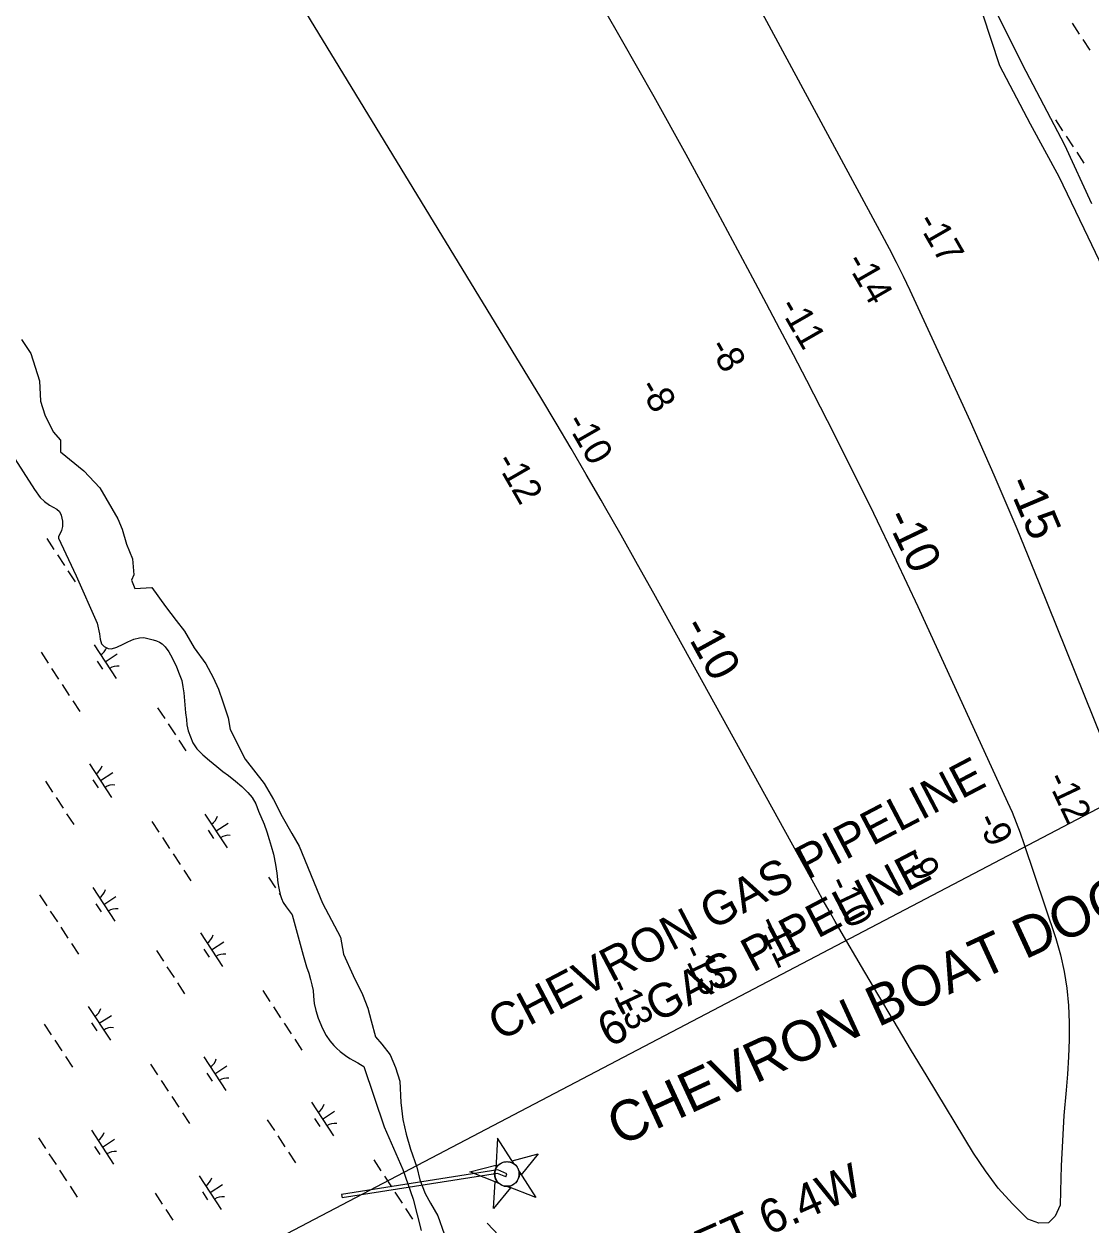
# Model space of a CAD drawing. Extents: x 3945642 to 3966284, y 206476 to 228921.
# Drawn here: x 3958060 to 3959382, y 212666 to 214156 of the extents above; entities that cross this region are included whole.
import ezdxf

# ---------------------------------------------------------------- set-up
doc = ezdxf.new("R2010")
doc.units = 0
for name, color, linetype in [('V-CHAN-DOCK', 7, 'Continuous'), ('V-CHAN-NAID', 7, 'Continuous'), ('V-RIVR-EDGE', 7, 'Continuous'), ('V-RIVR-RANG', 7, 'Continuous'), ('V-RRAP-DIKE', 7, 'Continuous'), ('V-RRAP-SILL-IDEN', 7, 'Continuous'), ('V-TOPO-DPTH', 7, 'Continuous'), ('V-TOPO-MINR', 7, 'Continuous'), ('V-TOPO-MINR-IDEN', 7, 'Continuous'), ('V-UTIL-IDEN', 7, 'Continuous'), ('V-UTIL-LINE', 7, 'Continuous'), ('V-WETL-SWMP', 7, 'Continuous')]:
    doc.layers.add(name, color=color, linetype=linetype)

msp = doc.modelspace()

# ---------------------------------------------------------------- linework, layer by layer
at = {"layer": 'V-CHAN-DOCK'}
for p, q in [((3958656.8, 212725.9), (3958658.4, 212729.6)), ((3958453.2, 212704.1), (3958453.9, 212700.2))]:
    msp.add_line(p, q, dxfattribs=at)
for points in [[(3958658.4, 212729.6), (3958647.1, 212734.6), (3958453.2, 212704.1)], [(3958656.8, 212725.9), (3958646.5, 212730.4), (3958453.9, 212700.2)]]:
    msp.add_lwpolyline(points, dxfattribs=at)
at = {"layer": 'V-CHAN-NAID'}
for points in [[(3958667.4, 212742), (3958646.7, 212774.1), (3958644.5, 212735.9), (3958645, 212736.9), (3958645.5, 212737.7), (3958646.1, 212738.6), (3958646.7, 212739.5), (3958647.2, 212740), (3958647.8, 212740.6), (3958648.3, 212741.1), (3958648.9, 212741.6), (3958649.6, 212742.1), (3958650.3, 212742.5), (3958651.2, 212743.1), (3958651.9, 212743.4), (3958652.9, 212743.9), (3958653.9, 212744.2), (3958654.8, 212744.5), (3958655.7, 212744.6), (3958656.6, 212744.8), (3958657.4, 212744.8), (3958658.5, 212744.9), (3958659.3, 212744.8), (3958660.2, 212744.8), (3958660.9, 212744.7), (3958661.8, 212744.5), (3958662.5, 212744.3), (3958663.6, 212744), (3958664.3, 212743.7), (3958665.2, 212743.3), (3958666, 212742.8), (3958666.7, 212742.4)], [(3958667.4, 212742), (3958664.8, 212746), (3958697.1, 212754.5), (3958676, 212728.6), (3958673.4, 212732.6), (3958673.2, 212733.5), (3958672.9, 212734.5), (3958672.5, 212735.5), (3958672.1, 212736.4), (3958671.8, 212736.9), (3958671.4, 212737.6), (3958670.9, 212738.3), (3958670.5, 212738.9), (3958669.9, 212739.6), (3958669.5, 212740.1), (3958668.8, 212740.8), (3958668.2, 212741.3), (3958667.8, 212741.6)], [(3958648.1, 212718.4), (3958612.4, 212732.2), (3958644.8, 212740.7), (3958644.5, 212735.9), (3958644.3, 212735.4), (3958643.9, 212734.3), (3958643.6, 212733.4), (3958643.4, 212732.4), (3958643.2, 212731.5), (3958643.2, 212730.6), (3958643.1, 212729.7), (3958643.2, 212728.7), (3958643.2, 212727.8), (3958643.4, 212726.8), (3958643.6, 212726), (3958643.8, 212725.2), (3958644.2, 212724.1), (3958644.5, 212723.4), (3958644.9, 212722.5), (3958645.3, 212721.8), (3958645.8, 212721), (3958646.3, 212720.3), (3958646.8, 212719.7), (3958647.5, 212719)], [(3958658.4, 212714.3), (3958662.9, 212712.6), (3958641.7, 212686.7), (3958643.6, 212720.1), (3958648.1, 212718.4), (3958648.7, 212717.8), (3958649.4, 212717.3), (3958650.4, 212716.6), (3958651.2, 212716.1), (3958652.2, 212715.7), (3958653.2, 212715.3), (3958654.1, 212714.9), (3958655, 212714.7), (3958655.9, 212714.5), (3958656.9, 212714.4), (3958657.8, 212714.4)], [(3958673.4, 212732.6), (3958694.1, 212700.5), (3958658.4, 212714.3), (3958659.3, 212714.4), (3958660.3, 212714.5), (3958661.2, 212714.6), (3958662.2, 212714.8), (3958663.1, 212715.1), (3958663.9, 212715.4), (3958664.8, 212715.8), (3958665.5, 212716.1), (3958666.5, 212716.7), (3958667.4, 212717.2), (3958668.2, 212717.9), (3958668.9, 212718.5), (3958669.7, 212719.3), (3958670.4, 212720.2), (3958671, 212721), (3958671.5, 212721.7), (3958672, 212722.7), (3958672.4, 212723.6), (3958672.8, 212724.5), (3958673.1, 212725.5), (3958673.3, 212726.4), (3958673.5, 212727.5), (3958673.6, 212728.6), (3958673.7, 212729.6), (3958673.6, 212730.7), (3958673.5, 212731.6)]]:
    msp.add_lwpolyline(points, close=True, dxfattribs=at)
msp.add_circle((3958658.4, 212729.6), 15.3, dxfattribs=at)
at = {"layer": 'V-RIVR-EDGE'}
for points in [[(3959247.9, 214168.6), (3959269.2, 214104.5), (3959307.2, 214032.1), (3959342.8, 213966.8), (3959378.5, 213892), (3959460.4, 213721), (3959496, 213645), (3959528, 213573.8), (3959594.5, 213443.2), (3959699, 213187.9), (3959765.5, 213045.5), (3959799.9, 212969.5), (3959840.3, 212872.1), (3959899.6, 212713.1), (3959916.3, 212675.1), (3959957.8, 212573)], [(3958056.4, 213764.5), (3958068.2, 213747.4), (3958078.7, 213713.3), (3958080, 213688.3), (3958085.3, 213671.2), (3958095.8, 213650.2), (3958105, 213639.7), (3958105, 213625.2), (3958133.9, 213601.6), (3958153.6, 213580.5), (3958176, 213542.4), (3958181.2, 213529.3), (3958186.5, 213510.9), (3958194.3, 213492.5), (3958195.7, 213472.8), (3958193, 213466.2), (3958197, 213455.7), (3958218, 213457), (3958235.1, 213433.3), (3958248.2, 213416.3), (3958258.7, 213403.1), (3958270.6, 213382.1), (3958285, 213362.4), (3958294.2, 213345.3), (3958300.8, 213330.8), (3958306.1, 213315.1), (3958312.6, 213295.4), (3958315.3, 213280.9), (3958333.7, 213244.1), (3958357.3, 213213.9), (3958369.1, 213194.2), (3958379.6, 213173.1), (3958391.5, 213152.1), (3958400.7, 213136.3), (3958429.6, 213065.4), (3958451.9, 213023.3), (3958455.9, 213002.3), (3958467.7, 212976), (3958479.5, 212952.4), (3958486.1, 212935.3), (3958490, 212919.5), (3958495.3, 212899.8), (3958503.2, 212890.6), (3958513.7, 212877.4), (3958520.3, 212861.7), (3958525.5, 212844.6), (3958526.8, 212818.3), (3958529.5, 212797.3), (3958533.4, 212778.9), (3958538.7, 212760.5), (3958546.5, 212738.1), (3958550.5, 212722.4), (3958557.1, 212705.3), (3958563.6, 212693.5), (3958572.8, 212677.7), (3958580.7, 212655.4)]]:
    msp.add_lwpolyline(points, dxfattribs=at)
at = {"layer": 'V-RRAP-DIKE'}
msp.add_lwpolyline([(3958633.8, 212668.5), (3958648.4, 212653.4)], dxfattribs=at)
at = {"layer": 'V-TOPO-DPTH'}
for points in [[(3959349.4, 212980.8), (3959352.6, 212959.9), (3959354.7, 212938.7), (3959355.5, 212917.4), (3959355.6, 212896.1), (3959354.8, 212874.8), (3959353.3, 212853.5), (3959351.5, 212833.5), (3959349, 212802.2), (3959347, 212770.9), (3959345.6, 212739.6), (3959344.7, 212708.2), (3959344.4, 212690.8), (3959338.2, 212677.4), (3959329.8, 212669.2), (3959318, 212668.8), (3959304.1, 212673.6), (3959285.2, 212692.4), (3959267.6, 212712.2), (3959251.7, 212733.5), (3959236.9, 212755.6), (3959179.4, 212850.4), (3959158.8, 212884.4), (3959138.4, 212918.6), (3959118.1, 212952.8), (3959097.9, 212987.1), (3959072.9, 213030), (3959065.4, 213042.9), (3959057.9, 213055.9), (3959050.6, 213069), (3959043.3, 213082), (3958860.3, 213413.6), (3958840.3, 213449.8), (3958820.2, 213485.8), (3958799.9, 213521.8), (3958779.5, 213557.8), (3958775.1, 213565.4), (3958756.7, 213597.4), (3958738.1, 213629.3), (3958719.3, 213661), (3958700.2, 213692.6), (3958323, 214311.9)], [(3958759.3, 214208.4), (3958800.1, 214137.4), (3958840.5, 214066.1), (3958880.1, 213994.4), (3958919.3, 213922.4), (3958962.9, 213841.1), (3958979.8, 213809.5), (3958996.5, 213777.9), (3959013.1, 213746.1), (3959029.6, 213714.3), (3959055.5, 213664), (3959084.5, 213606.7), (3959112.9, 213549.3), (3959140.6, 213491.4), (3959167.7, 213433.3), (3959279.1, 213190.9), (3959284.6, 213178.3), (3959289.9, 213165.5), (3959294.7, 213152.7), (3959299.3, 213139.7), (3959338.7, 213021.9), (3959344.6, 213001.5), (3959349.4, 212980.8)]]:
    msp.add_lwpolyline(points, dxfattribs=at)
at = {"layer": 'V-TOPO-MINR'}
for points in [[(3958708.5, 214663.2), (3959123.3, 213894.7), (3959132.3, 213877.7), (3959141.1, 213860.5), (3959149.6, 213843.2), (3959157.9, 213825.8), (3959202.7, 213729.3), (3959232.7, 213663.3), (3959262.1, 213597), (3959290.4, 213530.3), (3959318, 213463.2), (3959643.8, 212653.8)], [(3959349.4, 212980.8), (3959352.6, 212959.9), (3959354.7, 212938.7), (3959355.5, 212917.4), (3959355.6, 212896.1), (3959354.8, 212874.8), (3959353.3, 212853.5), (3959351.5, 212833.5), (3959349, 212802.2), (3959347, 212770.9), (3959345.6, 212739.6), (3959344.7, 212708.2), (3959344.4, 212690.8), (3959338.2, 212677.4), (3959329.8, 212669.2), (3959318, 212668.8), (3959304.1, 212673.6), (3959285.2, 212692.4), (3959267.6, 212712.2), (3959251.7, 212733.5), (3959236.9, 212755.6), (3959179.4, 212850.4), (3959158.8, 212884.4), (3959138.4, 212918.6), (3959118.1, 212952.8), (3959097.9, 212987.1), (3959072.9, 213030), (3959065.4, 213042.9), (3959057.9, 213055.9), (3959050.6, 213069), (3959043.3, 213082), (3958860.3, 213413.6), (3958840.3, 213449.8), (3958820.2, 213485.8), (3958799.9, 213521.8), (3958779.5, 213557.8), (3958775.1, 213565.4), (3958756.7, 213597.4), (3958738.1, 213629.3), (3958719.3, 213661), (3958700.2, 213692.6), (3958323, 214311.9)], [(3958759.3, 214208.4), (3958800.1, 214137.4), (3958840.5, 214066.1), (3958880.1, 213994.4), (3958919.3, 213922.4), (3958962.9, 213841.1), (3958979.8, 213809.5), (3958996.5, 213777.9), (3959013.1, 213746.1), (3959029.6, 213714.3), (3959055.5, 213664), (3959084.5, 213606.7), (3959112.9, 213549.3), (3959140.6, 213491.4), (3959167.7, 213433.3), (3959279.1, 213190.9), (3959284.6, 213178.3), (3959289.9, 213165.5), (3959294.7, 213152.7), (3959299.3, 213139.7), (3959338.7, 213021.9), (3959344.6, 213001.5), (3959349.4, 212980.8)]]:
    msp.add_lwpolyline(points, dxfattribs=at)
at = {"layer": 'V-UTIL-LINE'}
msp.add_line((3960018.1, 213511.7), (3958267, 212593.4), dxfattribs=at)
at = {"layer": 'V-WETL-SWMP'}
for p, q in [((3959259.3, 214182.1), (3959301.7, 214097.3)), ((3959359.2, 214157), (3959368, 214143.6)), ((3959372.4, 214136.9), (3959381.1, 214123.5)), ((3959301.7, 214097.3), (3959349.7, 214006.3)), ((3959338.5, 214037.1), (3959347.2, 214023.7)), ((3959351.6, 214017), (3959360.4, 214003.6)), ((3959349.7, 214006.3), (3959383.3, 213933.4)), ((3959364.8, 213996.9), (3959373.5, 213983.5)), ((3958012.7, 213671.8), (3958072.8, 213578.6)), ((3958072.8, 213578.6), (3958079.8, 213568.9)), ((3958079.8, 213568.9), (3958085, 213563.8)), ((3958085, 213563.8), (3958091.2, 213559.3)), ((3958091.2, 213559.3), (3958095.9, 213556.9)), ((3958095.9, 213556.9), (3958100.2, 213554.4)), ((3958100.2, 213554.4), (3958103.5, 213551.2)), ((3958103.5, 213551.2), (3958105.8, 213546.8)), ((3958105.8, 213546.8), (3958107.4, 213539.2)), ((3958107.4, 213539.2), (3958107.5, 213532.9)), ((3958104.4, 213523.9), (3958102.6, 213520.4)), ((3958106.2, 213527.9), (3958104.4, 213523.9)), ((3958107.5, 213532.9), (3958106.2, 213527.9)), ((3958087.8, 213517.8), (3958096.6, 213504.4)), ((3958102.6, 213520.4), (3958102.6, 213518.3)), ((3958102.6, 213518.3), (3958105.1, 213511.9)), ((3958105.1, 213511.9), (3958124.5, 213471.5)), ((3958101, 213497.7), (3958109.7, 213484.3)), ((3958114.1, 213477.6), (3958122.9, 213464.2)), ((3958124.5, 213471.5), (3958150.4, 213412.7)), ((3958150.4, 213412.7), (3958153.2, 213399.7)), ((3958153.2, 213399.7), (3958154.2, 213392.9)), ((3958154.2, 213392.9), (3958155.8, 213387.1)), ((3958182.6, 213386.6), (3958188.2, 213389.5)), ((3958188.2, 213389.5), (3958196, 213392.8)), ((3958196, 213392.8), (3958202.8, 213394.7)), ((3958202.8, 213394.7), (3958208.1, 213395)), ((3958208.1, 213395), (3958213.3, 213393.8)), ((3958213.3, 213393.8), (3958219.7, 213392.2)), ((3958219.7, 213392.2), (3958223.9, 213390.8)), ((3958223.9, 213390.8), (3958227.5, 213389.1)), ((3958227.5, 213389.1), (3958231.1, 213387)), ((3958080.7, 213376.8), (3958089.4, 213363.4)), ((3958146.5, 213385.9), (3958173.9, 213344.1)), ((3958155.8, 213387.1), (3958159.1, 213383.7)), ((3958159.1, 213383.7), (3958163.9, 213381.5)), ((3958160.2, 213365), (3958175.2, 213374.9)), ((3958163.9, 213381.5), (3958168.1, 213381.1)), ((3958168.1, 213381.1), (3958174.8, 213383.1)), ((3958174.8, 213383.1), (3958182.6, 213386.6)), ((3958231.1, 213387), (3958234.8, 213383.4)), ((3958234.8, 213383.4), (3958239.2, 213377.2)), ((3958239.2, 213377.2), (3958243.2, 213369.8)), ((3958150.4, 213365.8), (3958157, 213355.8)), ((3958243.2, 213369.8), (3958248.8, 213358.7)), ((3958248.8, 213358.7), (3958252.2, 213349.8)), ((3958093.8, 213356.7), (3958102.6, 213343.3)), ((3958252.2, 213349.8), (3958255.1, 213341.9)), ((3958107, 213336.6), (3958115.7, 213323.3)), ((3958255.1, 213341.9), (3958256.5, 213333.8)), ((3958256.5, 213333.8), (3958257.7, 213326.5)), ((3958120.1, 213316.6), (3958128.9, 213303.2)), ((3958257.7, 213326.5), (3958259.8, 213301.5)), ((3958225.3, 213307.8), (3958234.1, 213294.5)), ((3958259.8, 213301.5), (3958260.9, 213293.4)), ((3958238.5, 213287.8), (3958247.3, 213274.4)), ((3958260.9, 213293.4), (3958261.7, 213286.6)), ((3958261.7, 213286.6), (3958263.1, 213279.3)), ((3958263.1, 213279.3), (3958268.9, 213264.6)), ((3958251.6, 213267.7), (3958260.4, 213254.3)), ((3958268.9, 213264.6), (3958274.1, 213257)), ((3958274.1, 213257), (3958281.2, 213249.6)), ((3958281.2, 213249.6), (3958289.7, 213242.4)), ((3958289.7, 213242.4), (3958298.5, 213235.1)), ((3958140.9, 213238.5), (3958168.3, 213196.7)), ((3958154.6, 213217.6), (3958169.7, 213227.5)), ((3958298.5, 213235.1), (3958306.3, 213228.9)), ((3958306.3, 213228.9), (3958313.3, 213223.7)), ((3958086.2, 213216.7), (3958095, 213203.3)), ((3958144.9, 213218.4), (3958151.4, 213208.4)), ((3958313.3, 213223.7), (3958321.9, 213217)), ((3958321.9, 213217), (3958329.8, 213210.3)), ((3958329.8, 213210.3), (3958337.2, 213202.7)), ((3958099.4, 213196.6), (3958108.1, 213183.2)), ((3958337.2, 213202.7), (3958342.3, 213196.4)), ((3958342.3, 213196.4), (3958346.9, 213188.6)), ((3958346.9, 213188.6), (3958350.2, 213179.6)), ((3958112.5, 213176.5), (3958121.3, 213163.2)), ((3958218.2, 213166.9), (3958226.9, 213153.5)), ((3958284, 213176), (3958311.4, 213134.2)), ((3958297.7, 213155.1), (3958312.7, 213164.9)), ((3958350.2, 213179.6), (3958357.5, 213163.4)), ((3958287.9, 213155.9), (3958294.5, 213145.8)), ((3958357.5, 213163.4), (3958360.6, 213154)), ((3958360.6, 213154), (3958363.4, 213144.7)), ((3958231.3, 213146.8), (3958240.1, 213133.4)), ((3958363.4, 213144.7), (3958365.9, 213136.3)), ((3958365.9, 213136.3), (3958369, 213126.3)), ((3958244.5, 213126.7), (3958253.2, 213113.3)), ((3958369, 213126.3), (3958371.5, 213113.5)), ((3958257.6, 213106.6), (3958266.4, 213093.3)), ((3958371.5, 213113.5), (3958373.2, 213102.8)), ((3958362.9, 213097.9), (3958371.6, 213084.5)), ((3958373.2, 213102.8), (3958374.5, 213090.8)), ((3958374.5, 213090.8), (3958375.5, 213084.1)), ((3958079, 213075.7), (3958087.8, 213062.3)), ((3958144.8, 213084.8), (3958172.2, 213043)), ((3958375.5, 213084.1), (3958377.2, 213076.4)), ((3958376, 213077.9), (3958377.3, 213075.8)), ((3958377.2, 213076.4), (3958378.9, 213071.5)), ((3958148.8, 213064.7), (3958155.4, 213054.7)), ((3958158.5, 213063.9), (3958173.6, 213073.8)), ((3958378.9, 213071.5), (3958381.1, 213066.5)), ((3958381.1, 213066.5), (3958384.8, 213061.1)), ((3958384.8, 213061.1), (3958388.2, 213056.2)), ((3958092.2, 213055.6), (3958101, 213042.3)), ((3958388.2, 213056.2), (3958392, 213050.9)), ((3958392, 213050.9), (3958405.9, 213001)), ((3958105.3, 213035.6), (3958114.1, 213022.2)), ((3958278.4, 213028.6), (3958305.8, 212986.8)), ((3958292.1, 213007.7), (3958307.2, 213017.6)), ((3958118.5, 213015.5), (3958127.3, 213002.1)), ((3958223.7, 213006.8), (3958232.5, 212993.4)), ((3958282.4, 213008.5), (3958289, 212998.5)), ((3958405.9, 213001), (3958409.9, 212986.6)), ((3958236.9, 212986.7), (3958245.6, 212973.3)), ((3958409.9, 212986.6), (3958412.6, 212978.9)), ((3958412.6, 212978.9), (3958415, 212970.9)), ((3958250, 212966.6), (3958258.8, 212953.2)), ((3958355.7, 212957), (3958364.5, 212943.6)), ((3958415, 212970.9), (3958416.6, 212964.2)), ((3958416.6, 212964.2), (3958418.1, 212957.3)), ((3958418.1, 212957.3), (3958418.7, 212950)), ((3958418.7, 212950), (3958419.5, 212941.1)), ((3958139.3, 212937.5), (3958166.7, 212895.6)), ((3958368.9, 212936.9), (3958377.6, 212923.5)), ((3958419.5, 212941.1), (3958421.5, 212932.4)), ((3958421.5, 212932.4), (3958424.5, 212922.8)), ((3958084.6, 212915.6), (3958093.4, 212902.2)), ((3958143.2, 212917.3), (3958149.8, 212907.3)), ((3958153, 212916.6), (3958168, 212926.4)), ((3958382, 212916.8), (3958390.8, 212903.4)), ((3958424.5, 212922.8), (3958429.7, 212910)), ((3958395.2, 212896.7), (3958403.9, 212883.3)), ((3958429.7, 212910), (3958434.4, 212901.5)), ((3958434.4, 212901.5), (3958439, 212894.8)), ((3958097.7, 212895.6), (3958106.5, 212882.2)), ((3958439, 212894.8), (3958443.6, 212889.1)), ((3958443.6, 212889.1), (3958447, 212885.6)), ((3958447, 212885.6), (3958451.8, 212881.4)), ((3958110.9, 212875.5), (3958119.7, 212862.1)), ((3958282.4, 212874.9), (3958309.8, 212833.1)), ((3958451.8, 212881.4), (3958458.1, 212876.5)), ((3958458.1, 212876.5), (3958463.5, 212872.9)), ((3958463.5, 212872.9), (3958468.2, 212870.3)), ((3958468.2, 212870.3), (3958473.4, 212867.4)), ((3958473.4, 212867.4), (3958476.9, 212865.3)), ((3958216.6, 212865.8), (3958225.3, 212852.4)), ((3958286.3, 212854.8), (3958292.9, 212844.8)), ((3958296.1, 212854), (3958311.1, 212863.9)), ((3958476.9, 212865.3), (3958480.8, 212862.9)), ((3958480.8, 212862.9), (3958506.3, 212787.9)), ((3958229.7, 212845.7), (3958238.5, 212832.3)), ((3958242.9, 212825.6), (3958251.6, 212812.3)), ((3958415.9, 212818.7), (3958443.3, 212776.9)), ((3958429.6, 212797.8), (3958444.7, 212807.6)), ((3958256, 212805.6), (3958264.8, 212792.2)), ((3958361.2, 212796.9), (3958370, 212783.5)), ((3958419.9, 212798.6), (3958426.5, 212788.5)), ((3958143.2, 212783.8), (3958170.6, 212741.9)), ((3958506.3, 212787.9), (3958529.2, 212735.2)), ((3958077.4, 212774.6), (3958086.2, 212761.3)), ((3958147.2, 212763.7), (3958153.7, 212753.6)), ((3958156.9, 212762.9), (3958172, 212772.7)), ((3958374.4, 212776.8), (3958383.2, 212763.4)), ((3958090.6, 212754.6), (3958099.3, 212741.2)), ((3958387.6, 212756.7), (3958396.3, 212743.3)), ((3958103.7, 212734.5), (3958112.5, 212721.1)), ((3958493.2, 212747), (3958502, 212733.6)), ((3958529.2, 212735.2), (3958542.2, 212698.3)), ((3958276.8, 212727.5), (3958304.2, 212685.7)), ((3958506.4, 212727), (3958515.1, 212713.6)), ((3958116.9, 212714.4), (3958125.6, 212701)), ((3958222.1, 212705.7), (3958230.9, 212692.3)), ((3958280.8, 212707.4), (3958287.3, 212697.4)), ((3958290.5, 212706.6), (3958305.6, 212716.5)), ((3958519.5, 212706.9), (3958528.3, 212693.5)), ((3958542.2, 212698.3), (3958552.2, 212659.5)), ((3958235.3, 212685.6), (3958244, 212672.2)), ((3958532.7, 212686.8), (3958541.4, 212673.4))]:
    msp.add_line(p, q, dxfattribs=at)
for centre, start, end in [((3958145.2, 213388.2), 302.4575, 340.8016), ((3958175.5, 213342), 82.4574, 124.0011), ((3958139.7, 213240.9), 302.4575, 344.0011), ((3958169.9, 213194.6), 82.4574, 124.0011), ((3958282.7, 213178.3), 302.4575, 344.0011), ((3958313, 213132.1), 82.4574, 124.0011), ((3958143.6, 213087.2), 302.4575, 344.0011), ((3958173.9, 213041), 82.4574, 124.0011), ((3958277.2, 213030.9), 302.4575, 344.0011), ((3958307.5, 212984.7), 82.4574, 124.0011), ((3958138, 212939.8), 302.4575, 344.0011), ((3958168.3, 212893.6), 82.4574, 124.0011), ((3958281.1, 212877.2), 302.4575, 344.0011), ((3958311.4, 212831), 82.4574, 124.0011), ((3958414.7, 212821), 302.4575, 344.0011), ((3958445, 212774.8), 82.4574, 124.0011), ((3958142, 212786.1), 302.4575, 344.0011), ((3958172.2, 212739.9), 82.4574, 124.0011), ((3958275.6, 212729.9), 302.4575, 344.0011), ((3958305.8, 212683.7), 82.4574, 124.0011)]:
    msp.add_arc(centre, 17.6, start, end, dxfattribs=at)

# ---------------------------------------------------------------- texts
at = {"layer": 'V-CHAN-NAID'}
msp.add_text('CHEVRON BOAT DOCK', height=50, rotation=24.7477, dxfattribs=at).set_placement((3958797.9, 212763.6))
at = {"layer": 'V-RIVR-RANG'}
for s, rotation, p in [('-17', 299.8959, (3959165.6, 213911.1)), ('-14', 299.8959, (3959077.4, 213861.5)), ('-11', 299.8959, (3958994.3, 213805.8)), ('-8', 299.8959, (3958907.7, 213755.6)), ('-8', 299.8959, (3958821, 213705.7)), ('-10', 299.8959, (3958730.4, 213662.6)), ('-12', 299.8959, (3958643.3, 213613.6)), ('-12', 295.2871, (3959326.6, 213220)), ('-9', 295.2871, (3959240, 213169.1)), ('-9', 295.2871, (3959149.6, 213126.4)), ('-10', 295.2871, (3959055.7, 213091)), ('-11', 295.2871, (3958968.4, 213041.6)), ('-13', 295.2871, (3958874.3, 213006.6)), ('-13', 295.2871, (3958783.9, 212964))]:
    msp.add_text(s, height=33.5, rotation=rotation, dxfattribs=at).set_placement(p)
at = {"layer": 'V-RRAP-SILL-IDEN'}
msp.add_text('OUTLET 6.4W', height=42, rotation=23.9067, dxfattribs=at).set_placement((3958765.8, 212556.8))
at = {"layer": 'V-TOPO-MINR-IDEN'}
for s, rotation, p in [('-15', 292.9741, (3959277.7, 213586.6)), ('-10', 295.5641, (3959126.9, 213544.1)), ('-10', 298.8911, (3958875.1, 213408.4))]:
    msp.add_text(s, height=41.5, rotation=rotation, dxfattribs=at).set_placement(p)
at = {"layer": 'V-UTIL-IDEN'}
for s, p in [('CHEVRON GAS PIPELINE', (3958649.6, 212894)), ('6" GAS PIPELINE', (3958785.2, 212885.8))]:
    msp.add_text(s, height=42, rotation=27.6729, dxfattribs=at).set_placement(p)

doc.saveas('drawing.dxf')
